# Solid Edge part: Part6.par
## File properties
Author: user
Template: iso part.par
Last saved by: user
Revision: 2
Application: Solid Edge
Accuracy: 0.990
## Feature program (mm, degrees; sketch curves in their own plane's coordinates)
sketch for "unnamed RevolvedProtrusion 1" plane through (0, 0, 0) normal (0, -1, 0) x-axis (1, 0, 0)
  line (100, 0) -> (0, 500)
  line (0, 0) -> (0, 500)
  line (0, 0) -> (100, 0)
revolve "unnamed RevolvedProtrusion 1" add finite 360 deg
sketch for "unnamed Cutout 1" plane through (0, 0, 0) normal (0, -1, 0) x-axis (1, 0, 0)
  line (60, 350) -> (-60, 350)
extrude "unnamed Cutout 1" cut finite 300 symmetric
sketch for "Hole_1" plane through (0, 0, 350) normal (0, 0, 1) x-axis (1, 0, 0)
  hole centre (0, 0) bore radius 10
hole "Hole_1" diameter 20 through
sketch for "Hole_2" plane through (0, 0, 0) normal (0, 0, -1) x-axis (1, 0, 0)
  hole centre (0, 0) bore radius 50
hole "Hole_2" diameter 100 finite
sketch for "Hole_3" plane through (0, 0, 50) normal (0, 0, -1) x-axis (1, 0, 0)
  hole centre (0, 0) bore radius 30
hole "Hole_3" diameter 60 finite
fillet "Round_1" radius 5
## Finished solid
Body 1: solid body, 9 faces, 9 edges, 0 vertices.
  Faces by surface: plane 4, cylinder 3, cone 1, torus 1
  Edges by curve: circle 9
Bounding box of the edges (mm; curved faces can reach further): 200.000 x 200.000 x 350.000, from (-100, -100, 0) to (100, 100, 350).
Cylindrical faces by radius (mm): R10 x1, R30 x1, R50 x1
Conical faces (half-angle, radius in mm at the cone's reference point): 11.3099 deg R100 x1
Toroidal faces (ring radius, tube radius in mm): R25.901 r5 x1
Planar faces by outward normal: +z 1, -z 3
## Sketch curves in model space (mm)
line (60, 0, 350) -> (-60, 0, 350)
line (100, 0, 0) -> (0, 0, 500)
line (0, 0, 0) -> (100, 0, 0)
line (0, 0, 0) -> (0, 0, 500)
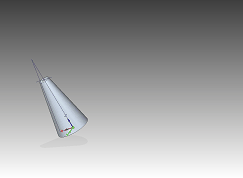
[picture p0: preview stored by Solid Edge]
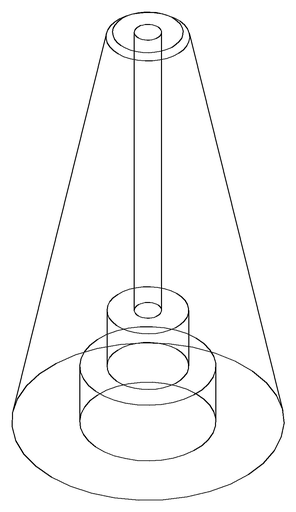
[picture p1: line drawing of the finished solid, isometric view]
